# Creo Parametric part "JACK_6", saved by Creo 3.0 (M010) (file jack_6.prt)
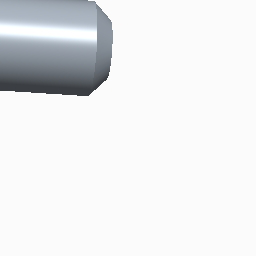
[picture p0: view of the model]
Units: millimeter Newton Second (mmNs); MM, TONNE, SECS

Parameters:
  PLACEMENT = "EXTERNAL"

Other parameters: MINOR_DIAMETER, PITCH

Created from: MMNS_PART_SOLID.PRT

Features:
  1. datum plane "RIGHT"
  2. datum plane "TOP"
  3. datum plane "FRONT"
  4. coordinate system
  5. protrusion
  6. chamfer
  7. chamfer
  8. cut
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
